// Mitsubishi GX Works2 project: jk2n modbus   PLC: FX2N/FX2NC

PROGRAM MAIN
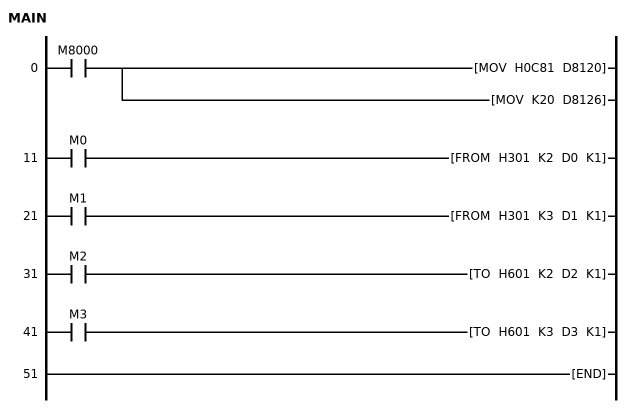
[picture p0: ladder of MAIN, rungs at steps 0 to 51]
0     LD      M8000
      MOV     H0C81 D8120
      MOV     K20 D8126
11    LD      M0
      FROM    H301 K2 D0 K1
21    LD      M1
      FROM    H301 K3 D1 K1
31    LD      M2
      TO      H601 K2 D2 K1
41    LD      M3
      TO      H601 K3 D3 K1
51    END
END_PROGRAM
